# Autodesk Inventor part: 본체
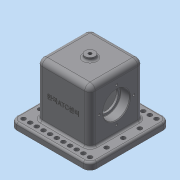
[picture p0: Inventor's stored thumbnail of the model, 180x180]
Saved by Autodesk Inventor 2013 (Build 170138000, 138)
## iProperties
Created: 2018-11
Part Number: 본체
Material: 일반
Document SubType Name: Modeling
Designer: dgall
Density: 1 g/cm^3
Author: dgall
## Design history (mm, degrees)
sketch "스케치1"
  geometry: L1 (-40, 40)-(40, 40); L2 (40, 40)-(40, -40); L3 (40, -40)-(-40, -40); L4 (-40, -40)-(-40, 40); 3 further points
  constraints: 8 end point, 2 midpoint, 2 parallel, 2 perpendicular, 1 horizontal, 1 horizontal alignment, 1 vertical alignment
  dimensions: "d0" = 80 distance of L1.start L1.end
extrude "돌출1" new body sketch "스케치1" distance "d2" = 90; taper "d3" = 0 deg
sketch "스케치2"
  geometry: L1 (-60, 60)-(60, 60); L2 (60, 60)-(60, -60); L3 (60, -60)-(-60, -60); L4 (-60, -60)-(-60, 60); L5 (-23, 30)-(23, 30); L6 (23, 30)-(23, -30); L7 (23, -30)-(-23, -30); L8 (-23, -30)-(-23, 30); 5 further points
  constraints: 16 end point, 4 midpoint, 4 parallel, 3 perpendicular, 2 horizontal, 2 horizontal alignment, 2 vertical alignment
  dimensions: "d4" = 120 distance of L1.start L1.end; "d6" = 60 distance of L5.end L6.end; "d7" = 46 distance of L5.start L5.end
extrude "돌출2" join sketch "스케치2" distance "d8" = 10; taper "d9" = 0 deg
extrude "돌출3" cut sketch "스케치2" distance "d10" = 80; taper "d11" = 0 deg
sketch "스케치3"
  geometry: L1 (-90, 100)-(-90, -20) reference; C1 r 20 at (-42, 40); 2 further points
  constraints: 1 centre point, 1 horizontal alignment, 1 midpoint
  dimensions: "d12" = 40 diameter of C1; "d13" = 48 distance from line of L1 C1.centre
extrude "돌출4" cut sketch "스케치3" distance "d14" = 14; taper "d15" = 0 deg
hole "구멍1" diameter "d18" = 33; stored, may be unused: countersink angle "d22" = 90 deg, drill point angle "d24" = 118 deg; dims "d16" = 10, "d17" = 10, "d19" = 6, "d20" = 4, "d21" = 2, "d23" = 8
fillet "모깎기1" dims "d25" = 10
fillet "모깎기2" dims "d26" = 8
fillet "모깎기3" dims "d27" = 3
node "작업 평면1"
sketch "스케치4"
  geometry: C1 r 7.5 at (0, 0); 1 further point
  constraints: 1 centre point, 1 coincident
  dimensions: "d29" = 15 diameter of C1
extrude "돌출5" join sketch "스케치4" stored distance "d30" = 14; taper "d31" = 0 deg
hole "구멍2" diameter "d34" = 4.917; stored, may be unused: countersink angle "d38" = 90 deg, drill point angle "d40" = 118 deg; dims "d32" = 10, "d33" = 10, "d35" = 6, "d36" = 4, "d37" = 2, "d39" = 8
fillet "모깎기4" dims "d41" = 3
sketch "스케치5"
  geometry: C1 r 3.3 at (-50, 50); C2 r 3.3 at (-50, 25); C3 r 3.3 at (-50, 0); C4 r 3.3 at (-50, -25); C5 r 3.3 at (-50, -50); C6 r 3.3 at (-40, 50); C7 r 3.3 at (-30, 50); C8 r 3.3 at (-20, 50); C9 r 3.3 at (-10, 50); C10 r 3.3 at (0, 50); C11 r 3.3 at (10, 50); C12 r 3.3 at (20, 50); C13 r 3.3 at (30, 50); C14 r 3.3 at (40, 50); C15 r 3.3 at (50, 50); A1 r 10 centre (-50, 50) between (-50, 60) and (-60, 50) reference; A2 r 10 centre (-50, -50) between (-60, -50) and (-50, -60) reference; 1 further point
  constraints: 15 centre point, 10 equal radius, 10 horizontal alignment, 4 vertical alignment, 2 coincident
  dimensions: "d42" = 6.6 diameter of C1; "d43" = 6.6 diameter of C2; "d44" = 6.6 diameter of C3; "d45" = 6.6 diameter of C4; "d46" = 6.6 diameter of C5; "d47" = 25 distance of C1.centre C2.centre; "d48" = 25 distance of C2.centre C3.centre; "d49" = 25 distance of C5.centre C4.centre; "d50" = 10 distance of C6.centre C1.centre; "d51" = 10 distance of C7.centre C6.centre; "d52" = 10 distance of C8.centre C7.centre; "d53" = 10 distance of C9.centre C8.centre; "d54" = 10 distance of C10.centre C9.centre; "d55" = 10 distance of C11.centre C10.centre; "d56" = 10 distance of C12.centre C11.centre; "d57" = 10 distance of C13.centre C12.centre; "d58" = 10 distance of C14.centre C13.centre; "d59" = 10 distance of C15.centre C14.centre
extrude "돌출6" cut sketch "스케치5" stored distance "d60" = 14; taper "d61" = 0 deg
extrude "돌출7" cut sketch "스케치5" stored distance "d62" = 14; taper "d63" = 0 deg
fillet "모깎기5" dims "d64" = 3
chamfer "모따기1" distance "d65" = 1; stored, may be unused: second distance "d66" = 2, angle "d67" = 45 deg
fillet "모깎기6" dims "d68" = 0.6
sketch "스케치6"
  geometry: L1 (-82, 82)-(-82, -18) reference; C1 r 16.5 at (-34, 32) reference; 3 further points
  constraints: 1 horizontal alignment, 1 midpoint
  dimensions: "d69" = 26 distance of C1.centre point (-8, 32)
hole "구멍3" sketch "스케치6" at (-8, 32) diameter "d70" = 3.242; stored, may be unused: countersink angle "d74" = 90 deg, drill point angle "d76" = 118 deg; dims "d71" = 8, "d72" = 4, "d73" = 2, "d75" = 10
sketch "스케치7"
  geometry: L1 (-18, -82)-(82, -82) reference; 3 further points
  constraints: 1 midpoint, 1 vertical alignment, 1 other
  dimensions: "d80" = 48 distance from line of L1 point (32, -34)
feature "엠보싱1" sketch "스케치7" dims "d0" = 80, "d10" = 80, "d81" = 0.5, "d82" = 0
node "솔리드1"
mirror "대칭1"
mirror "대칭2"
mirror "대칭3"
pattern_circular "원형 패턴1" dims angle "d78" = 360 deg
mirror "대칭4"
other parameters: "d28" = 5
